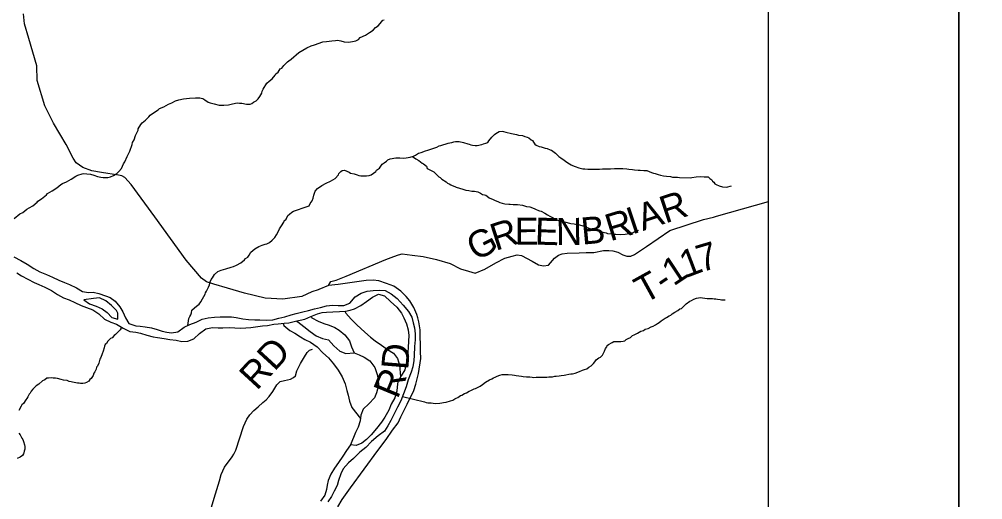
# Model space of a CAD drawing. Extents: x 0 to 39.3, y -3.9 to 22.
# Drawn here: x 7.125 to 9.15, y 19.017 to 20.026 of the extents above; entities that cross this region are included whole.
import ezdxf

# ---------------------------------------------------------------- set-up
doc = ezdxf.new("R2010")
doc.units = 0
for name, color, linetype in [('GM_X_Corporation', 7, 'Continuous'), ('GM_X_County_Road_Text', 7, 'Continuous'), ('GM_X_Major_River', 7, 'Continuous'), ('GM_X_Minor_River', 7, 'Continuous'), ('GM_X_Township_Road', 7, 'Continuous'), ('GM_X_Township_Road_Text', 7, 'Continuous'), ('SH_Data', 7, 'Continuous'), ('SH_Text', 7, 'Continuous')]:
    doc.layers.add(name, color=color, linetype=linetype)

msp = doc.modelspace()

# ---------------------------------------------------------------- linework, layer by layer
at = {"layer": 'GM_X_Corporation'}
msp.add_lwpolyline([(8.7, 17.1372), (8.7, 20.7), (3.278, 20.7)], dxfattribs=at)
at = {"layer": 'GM_X_Major_River'}
for points in [[(7.1136, 19.5274), (7.1283, 19.5199), (7.1414, 19.5121), (7.1554, 19.5031), (7.1681, 19.4957), (7.1821, 19.4905), (7.1949, 19.4846), (7.2081, 19.4787), (7.2202, 19.4735), (7.2304, 19.4692), (7.2451, 19.4625), (7.2579, 19.4547), (7.2708, 19.4529), (7.2803, 19.4531), (7.292, 19.4507), (7.3064, 19.4455), (7.3162, 19.4423), (7.3267, 19.4345), (7.3364, 19.4226), (7.3427, 19.4118), (7.3482, 19.3992), (7.3552, 19.3873), (7.3699, 19.3829), (7.3794, 19.3816), (7.3897, 19.3806), (7.4033, 19.3785), (7.4146, 19.3749), (7.4252, 19.3717), (7.4355, 19.3696), (7.4453, 19.3679), (7.4583, 19.37), (7.4717, 19.3797), (7.4836, 19.3852), (7.497, 19.3906), (7.5092, 19.3965), (7.5222, 19.3997), (7.5351, 19.401), (7.5473, 19.4016), (7.5572, 19.4018), (7.5708, 19.4012), (7.5807, 19.3999), (7.5947, 19.3974), (7.6068, 19.3961), (7.6201, 19.3951), (7.6304, 19.3949), (7.644, 19.3943), (7.6577, 19.3952), (7.6707, 19.3988), (7.6833, 19.4016), (7.6966, 19.4056), (7.7073, 19.4088), (7.7214, 19.412), (7.7333, 19.4149), (7.7459, 19.4185), (7.7584, 19.4213), (7.7706, 19.4245), (7.7832, 19.4262), (7.7957, 19.4256), (7.8075, 19.425), (7.8197, 19.4305), (7.8313, 19.4433), (7.844, 19.451), (7.8566, 19.4554), (7.8688, 19.4567), (7.8821, 19.4576), (7.8939, 19.4571), (7.9067, 19.4496), (7.9194, 19.4403), (7.9321, 19.426)], [(7.1202, 19.4938), (7.13, 19.4876), (7.1432, 19.4805), (7.156, 19.4738), (7.1658, 19.4691), (7.1786, 19.4636), (7.193, 19.4565), (7.2057, 19.4483), (7.2178, 19.4416), (7.2299, 19.4369), (7.2419, 19.4314), (7.2548, 19.4251), (7.2665, 19.4211), (7.2793, 19.4163), (7.2921, 19.4081), (7.3044, 19.3965), (7.3176, 19.3902), (7.3297, 19.3862), (7.3433, 19.378), (7.3572, 19.3709), (7.3701, 19.3696), (7.3799, 19.3671), (7.3932, 19.3631), (7.4064, 19.3595), (7.4159, 19.3578), (7.4295, 19.3557), (7.4417, 19.3539), (7.4545, 19.3522), (7.467, 19.3497), (7.4796, 19.3503), (7.4922, 19.3554), (7.5042, 19.3666), (7.5172, 19.3766), (7.531, 19.3791), (7.5431, 19.3785), (7.5526, 19.3787), (7.5659, 19.3789), (7.5781, 19.3787), (7.5906, 19.3777), (7.6012, 19.3783), (7.6119, 19.3792), (7.6263, 19.3809), (7.6362, 19.3826), (7.6465, 19.3836), (7.6599, 19.3864), (7.6694, 19.3867), (7.6819, 19.388), (7.6914, 19.389), (7.7055, 19.3925), (7.7154, 19.3943), (7.725, 19.3968), (7.738, 19.4022), (7.7518, 19.4081), (7.7617, 19.4106), (7.7712, 19.4116), (7.7841, 19.4121), (7.7982, 19.4127), (7.8107, 19.4136), (7.8203, 19.4153), (7.8298, 19.4186), (7.8428, 19.4252), (7.8551, 19.4338), (7.8674, 19.4431), (7.8801, 19.4493), (7.8929, 19.4457), (7.9056, 19.4337), (7.9184, 19.4221), (7.9284, 19.4094), (7.9336, 19.3994), (7.9387, 19.3868)], [(7.3324, 19.4093), (7.3294, 19.4147), (7.3186, 19.4251), (7.307, 19.4352), (7.2938, 19.4415), (7.2808, 19.4402), (7.2607, 19.4371)], [(7.2607, 19.4371), (7.2723, 19.4286), (7.2863, 19.4238), (7.2995, 19.4182), (7.31, 19.4105), (7.3197, 19.4), (7.3322, 19.3968), (7.3324, 19.4093)], [(7.9321, 19.426), (7.9433, 19.4129), (7.9499, 19.4006), (7.9528, 19.3892), (7.9557, 19.3785), (7.9574, 19.3656), (7.9572, 19.3534), (7.9558, 19.339), (7.9555, 19.32), (7.9546, 19.3101), (7.9521, 19.2968), (7.9485, 19.2851), (7.9425, 19.2689), (7.9381, 19.2545), (7.9329, 19.2401), (7.9274, 19.2254), (7.9203, 19.2118), (7.9062, 19.1839), (7.8999, 19.1726), (7.8925, 19.1617), (7.8798, 19.1513), (7.8656, 19.1394), (7.8532, 19.1274), (7.8409, 19.117), (7.8274, 19.1039), (7.817, 19.0946), (7.8061, 19.0822), (7.8007, 19.072), (7.7959, 19.0577), (7.7934, 19.0474), (7.7871, 19.0354), (7.7813, 19.0244), (7.7739, 19.0128)], [(7.9387, 19.3868), (7.9423, 19.3745), (7.9436, 19.3624), (7.9434, 19.3506), (7.9428, 19.3369), (7.9419, 19.327), (7.9406, 19.3176), (7.9385, 19.3031), (7.9352, 19.2899), (7.9278, 19.2779), (7.9208, 19.265), (7.9195, 19.2548), (7.9186, 19.2453), (7.9145, 19.2313), (7.9071, 19.2178), (7.9016, 19.2053), (7.8934, 19.191), (7.8867, 19.1805), (7.8763, 19.1669), (7.8647, 19.1535), (7.855, 19.1441), (7.8454, 19.1363), (7.8332, 19.1315), (7.821, 19.1329), (7.8132, 19.1209), (7.8051, 19.1088), (7.7961, 19.0957), (7.7879, 19.0836), (7.7801, 19.0708), (7.7746, 19.058), (7.7722, 19.0482), (7.7709, 19.0387), (7.7676, 19.0273), (7.7583, 19.0146)]]:
    msp.add_lwpolyline(points, dxfattribs=at)
at = {"layer": 'GM_X_Minor_River'}
for points in [[(7.6768, 19.924), (7.6814, 19.9292), (7.6888, 19.9371), (7.6915, 19.9393), (7.6965, 19.943), (7.7019, 19.9475), (7.7069, 19.9516), (7.7127, 19.9564), (7.7211, 19.9616), (7.7296, 19.9664), (7.7384, 19.9704), (7.7457, 19.9726), (7.7633, 19.9791), (7.7709, 19.9801), (7.7819, 19.9815), (7.7899, 19.9821), (7.7941, 19.9824), (7.8009, 19.9811), (7.8077, 19.9791), (7.8169, 19.9786), (7.8256, 19.9799), (7.8325, 19.9813), (7.8379, 19.9843), (7.8417, 19.988), (7.8525, 19.9932), (7.8613, 19.9987), (7.869, 20.0039), (7.874, 20.0091), (7.8794, 20.0128), (7.8837, 20.0173), (7.8891, 20.0245), (7.8922, 20.0255)], [(7.1145, 19.6079), (7.1265, 19.6176), (7.1322, 19.6206), (7.1411, 19.628), (7.1457, 19.6306), (7.1534, 19.635), (7.1626, 19.6421), (7.1642, 19.6447), (7.1715, 19.6492), (7.1823, 19.6577), (7.1846, 19.6607), (7.1938, 19.6659), (7.2038, 19.6725), (7.2123, 19.6796), (7.2161, 19.6818), (7.2242, 19.6851), (7.2341, 19.6906), (7.2441, 19.6973), (7.248, 19.6988), (7.2571, 19.7017), (7.2602, 19.7024), (7.267, 19.7022), (7.2746, 19.701), (7.2818, 19.6989), (7.2894, 19.6965), (7.2962, 19.6949), (7.3015, 19.694), (7.3072, 19.6939), (7.3114, 19.6942), (7.3171, 19.6957), (7.3232, 19.6986), (7.3298, 19.7027), (7.3344, 19.7068), (7.3398, 19.7131), (7.3438, 19.723), (7.3469, 19.7271), (7.3517, 19.738), (7.354, 19.7422), (7.3576, 19.7497), (7.3623, 19.7633), (7.3632, 19.7679), (7.3663, 19.7735), (7.3691, 19.7822), (7.3746, 19.7935), (7.3751, 19.7962), (7.3802, 19.8056), (7.3836, 19.8093), (7.3902, 19.8145), (7.3972, 19.8216), (7.4003, 19.8254), (7.4053, 19.8283), (7.4168, 19.8365), (7.4195, 19.8391), (7.4291, 19.8428), (7.4387, 19.8479), (7.4459, 19.8512), (7.4536, 19.8549), (7.4601, 19.857), (7.47, 19.8592), (7.4826, 19.8608), (7.4952, 19.8614), (7.5043, 19.8612), (7.5073, 19.8608), (7.5111, 19.86), (7.5152, 19.8572), (7.522, 19.8525), (7.5262, 19.8513), (7.5345, 19.8489), (7.5451, 19.8464), (7.555, 19.8459), (7.5645, 19.8469), (7.5729, 19.8486), (7.5832, 19.8507), (7.5877, 19.8506), (7.5931, 19.8502), (7.6025, 19.8485), (7.6078, 19.848), (7.6105, 19.8483), (7.6136, 19.8494), (7.6174, 19.8524), (7.6228, 19.8553), (7.6274, 19.8591), (7.6309, 19.864), (7.6349, 19.8715), (7.6357, 19.8753), (7.6376, 19.8794), (7.6451, 19.8926), (7.6501, 19.8963), (7.6563, 19.9015), (7.6632, 19.909), (7.6644, 19.9117), (7.6694, 19.9157), (7.6737, 19.9225), (7.6768, 19.924)], [(7.9964, 19.7557), (8.0025, 19.7582), (8.0078, 19.7604), (8.0113, 19.7615), (8.0178, 19.7637), (8.0205, 19.7644), (8.0266, 19.7666), (8.03, 19.7673), (8.0342, 19.7679), (8.0388, 19.7694), (8.0422, 19.7697), (8.0495, 19.77), (8.0589, 19.7679), (8.068, 19.7651), (8.0706, 19.7643), (8.0744, 19.7631), (8.0778, 19.7619), (8.0831, 19.7614), (8.0873, 19.7613), (8.0972, 19.7638), (8.1011, 19.7649), (8.106, 19.7663), (8.1099, 19.7678), (8.1122, 19.7715), (8.1184, 19.7786), (8.1242, 19.7842), (8.1269, 19.7865), (8.1338, 19.7909), (8.1399, 19.7916), (8.1429, 19.7908), (8.1479, 19.7891), (8.1596, 19.7867), (8.1706, 19.7842), (8.1744, 19.7834), (8.1831, 19.7825), (8.188, 19.7805), (8.1929, 19.7792), (8.1963, 19.7777), (8.2012, 19.7734), (8.2038, 19.7722), (8.2057, 19.7687), (8.209, 19.7645), (8.2117, 19.7618), (8.2181, 19.7594), (8.2222, 19.7586), (8.2306, 19.7558), (8.2347, 19.7549), (8.2412, 19.7525), (8.2438, 19.7514), (8.2494, 19.7475), (8.2524, 19.7451), (8.2595, 19.7381), (8.2633, 19.7358), (8.2704, 19.7307), (8.2734, 19.7288), (8.2783, 19.7253), (8.2855, 19.7206), (8.2881, 19.7194), (8.2934, 19.7174), (8.301, 19.7146), (8.3097, 19.7126), (8.3139, 19.7125), (8.3199, 19.712), (8.3348, 19.7117), (8.3412, 19.712), (8.345, 19.7119), (8.3511, 19.7122), (8.3599, 19.7124), (8.3678, 19.7127), (8.3766, 19.7129), (8.3891, 19.7131), (8.3941, 19.7134), (8.4024, 19.7121), (8.4062, 19.712), (8.4138, 19.7111), (8.418, 19.7103), (8.4263, 19.7098), (8.4305, 19.7093), (8.4377, 19.7088), (8.4446, 19.7087), (8.4491, 19.7067), (8.4544, 19.7047), (8.4582, 19.7031), (8.462, 19.7023), (8.4684, 19.7003), (8.4729, 19.6991), (8.4794, 19.6978), (8.4858, 19.6969), (8.4942, 19.696), (8.4983, 19.6952), (8.5021, 19.6951), (8.5086, 19.6946), (8.5128, 19.6942), (8.5352, 19.6938), (8.539, 19.6945), (8.5481, 19.6955), (8.5577, 19.6961), (8.5645, 19.6959), (8.5694, 19.6955), (8.5732, 19.6954), (8.577, 19.6919)], [(7.4794, 19.3832), (7.4813, 19.3981), (7.4836, 19.4022), (7.4856, 19.4056), (7.4872, 19.4098), (7.488, 19.4155), (7.4931, 19.4203), (7.4977, 19.424), (7.5035, 19.4281), (7.5066, 19.433), (7.5101, 19.439), (7.5156, 19.4492), (7.5164, 19.4522), (7.5184, 19.4556), (7.5227, 19.4639), (7.5251, 19.4688), (7.5263, 19.4753), (7.5283, 19.4798), (7.531, 19.4835), (7.5357, 19.4903), (7.5426, 19.4966), (7.5495, 19.4992), (7.5595, 19.5021), (7.5705, 19.5061), (7.5751, 19.5075), (7.582, 19.51), (7.5908, 19.5152), (7.5982, 19.5215), (7.6009, 19.5238), (7.6055, 19.5267), (7.6086, 19.5309), (7.6121, 19.5376), (7.6202, 19.544), (7.6287, 19.5495), (7.6356, 19.5521), (7.6421, 19.5539), (7.6455, 19.5546), (7.6509, 19.5575), (7.6563, 19.5624), (7.6621, 19.5683), (7.6656, 19.5736), (7.6687, 19.5789), (7.6719, 19.586), (7.6734, 19.5887), (7.6762, 19.5924), (7.6812, 19.6003), (7.682, 19.603), (7.6859, 19.6067), (7.6895, 19.6146), (7.6929, 19.6172), (7.6979, 19.6213), (7.7014, 19.6232), (7.7102, 19.6261), (7.7217, 19.6304), (7.7343, 19.6344), (7.7366, 19.6397), (7.7405, 19.6453), (7.7425, 19.6506), (7.7442, 19.6574), (7.7454, 19.6612), (7.747, 19.6653), (7.7516, 19.671), (7.7612, 19.6776), (7.7701, 19.6821), (7.7793, 19.6868), (7.7889, 19.6924), (7.7958, 19.6999), (7.7966, 19.7025), (7.8009, 19.7066), (7.804, 19.7092), (7.8089, 19.7099), (7.8187, 19.7052), (7.8214, 19.7032), (7.8289, 19.7016), (7.835, 19.6996), (7.8388, 19.6987), (7.8433, 19.6975), (7.8517, 19.6974), (7.8551, 19.6977), (7.8608, 19.6983), (7.865, 19.6998), (7.8746, 19.7065), (7.8758, 19.7095), (7.8824, 19.7139), (7.8878, 19.7222), (7.8921, 19.7248), (7.8971, 19.7285), (7.9001, 19.7311), (7.9047, 19.7337), (7.9166, 19.7358), (7.9253, 19.7352), (7.9329, 19.7347), (7.9382, 19.7354), (7.9466, 19.7368), (7.9539, 19.7393), (7.9577, 19.7411), (7.9643, 19.7456), (7.97, 19.7466), (7.9788, 19.7503), (7.9837, 19.7513), (7.9964, 19.7557)], [(7.9517, 19.7385), (7.9587, 19.7331), (7.9648, 19.7296), (7.9723, 19.7242), (7.9749, 19.723), (7.9809, 19.7179), (7.9823, 19.7133), (7.9884, 19.7106), (7.9963, 19.7059), (8.0008, 19.7016), (8.0071, 19.6958), (8.0098, 19.6942), (8.0135, 19.6907), (8.0226, 19.6852), (8.0255, 19.6825), (8.0289, 19.681), (8.0323, 19.679), (8.035, 19.6774), (8.0406, 19.675), (8.0437, 19.6739), (8.0505, 19.6715), (8.0576, 19.6694), (8.0637, 19.6674), (8.0698, 19.6666), (8.0762, 19.6657), (8.0789, 19.6656), (8.0819, 19.6652), (8.0887, 19.6639), (8.0944, 19.6616), (8.0989, 19.6588), (8.1027, 19.658), (8.1057, 19.6572), (8.1087, 19.6548), (8.1125, 19.6514), (8.1212, 19.6478), (8.1253, 19.6462), (8.131, 19.6438), (8.1351, 19.6418), (8.14, 19.6402), (8.1457, 19.639), (8.1541, 19.6381), (8.1567, 19.638), (8.1632, 19.6375), (8.1677, 19.6378), (8.1723, 19.6374), (8.1829, 19.6364), (8.1912, 19.6336), (8.1985, 19.6324), (8.2071, 19.6288), (8.2105, 19.628), (8.2162, 19.6252), (8.2188, 19.6244), (8.2223, 19.6236), (8.2298, 19.6196), (8.2354, 19.6157), (8.2403, 19.613), (8.2475, 19.6095), (8.252, 19.606), (8.2562, 19.6047), (8.263, 19.6023), (8.2671, 19.6011), (8.2739, 19.6002), (8.2819, 19.5982), (8.2846, 19.5978), (8.2914, 19.5965), (8.294, 19.5961), (8.2986, 19.5953), (8.3024, 19.5944), (8.3096, 19.5928), (8.316, 19.5908), (8.322, 19.588), (8.3292, 19.5856), (8.3318, 19.5844), (8.3372, 19.5832), (8.3436, 19.5815), (8.3489, 19.5803), (8.3587, 19.5778), (8.3618, 19.5767), (8.3697, 19.5758), (8.3735, 19.5753), (8.3788, 19.5748), (8.3899, 19.5746), (8.399, 19.5752), (8.4032, 19.5756), (8.4093, 19.5773), (8.4154, 19.5784), (8.4212, 19.5821), (8.4238, 19.5828), (8.4265, 19.5835)], [(8.577, 19.6919), (8.5807, 19.6892), (8.5822, 19.6865), (8.5848, 19.6842), (8.5874, 19.6807), (8.5901, 19.6795), (8.5965, 19.6764), (8.6033, 19.6747), (8.612, 19.6738), (8.622, 19.6767)], [(8.4144, 19.362), (8.4175, 19.3639), (8.4248, 19.3675), (8.4317, 19.3716), (8.437, 19.373), (8.4409, 19.3756), (8.447, 19.377), (8.4535, 19.3807), (8.4573, 19.3818), (8.4623, 19.3848), (8.4665, 19.3873), (8.4704, 19.3896), (8.4746, 19.3929), (8.4827, 19.3988), (8.4858, 19.4003), (8.4911, 19.4036), (8.4946, 19.4051), (8.4973, 19.4081), (8.5031, 19.4114), (8.5096, 19.4147), (8.5134, 19.4181), (8.5169, 19.4192), (8.5211, 19.4233), (8.5273, 19.4285), (8.5346, 19.4341), (8.5385, 19.4359), (8.5431, 19.4385), (8.5484, 19.4407), (8.5526, 19.4417), (8.5572, 19.442), (8.561, 19.4416), (8.5712, 19.4403), (8.575, 19.4402), (8.5826, 19.4401), (8.5857, 19.4396), (8.5891, 19.4396), (8.5929, 19.4388), (8.5982, 19.4379), (8.6012, 19.4375), (8.6088, 19.4373)], [(7.8096, 19.4135), (7.8118, 19.4095), (7.8229, 19.3963), (7.8345, 19.3844), (7.8514, 19.3693), (7.8634, 19.3588), (7.8735, 19.3514), (7.8863, 19.342), (7.8991, 19.3331), (7.9119, 19.3253), (7.9204, 19.3137), (7.9244, 19.3003), (7.9267, 19.2759)], [(7.6795, 19.3877), (7.6813, 19.3836), (7.694, 19.3731), (7.7042, 19.3672), (7.7159, 19.3598), (7.7256, 19.3539), (7.7373, 19.348), (7.7509, 19.3387), (7.7628, 19.3259), (7.7748, 19.3155), (7.7856, 19.3027), (7.7953, 19.2896), (7.8038, 19.2754), (7.81, 19.2609), (7.8139, 19.2471), (7.8164, 19.2372), (7.8193, 19.2246), (7.8244, 19.2112), (7.8421, 19.1878)], [(7.7073, 19.3928), (7.7103, 19.3907), (7.7231, 19.381), (7.7366, 19.3709), (7.7494, 19.3615), (7.7622, 19.3563), (7.7751, 19.3531), (7.7863, 19.3403), (7.799, 19.3291), (7.8115, 19.3243), (7.8293, 19.3258)], [(7.7384, 19.4024), (7.7401, 19.3997), (7.7533, 19.3926), (7.7654, 19.3878), (7.7767, 19.3842), (7.7881, 19.3791), (7.7978, 19.3736), (7.8091, 19.3639), (7.8195, 19.3512), (7.8235, 19.3382), (7.829, 19.3259), (7.8395, 19.3216), (7.8497, 19.3165), (7.8621, 19.309), (7.8722, 19.2952), (7.8776, 19.2802), (7.8797, 19.2699), (7.8799, 19.2574), (7.8758, 19.2419), (7.8715, 19.2317), (7.8598, 19.2186), (7.8479, 19.2078), (7.8427, 19.1953), (7.8417, 19.1828), (7.8373, 19.17), (7.8318, 19.1583), (7.821, 19.1329)], [(7.3397, 19.3801), (7.3395, 19.3777), (7.3372, 19.374), (7.3349, 19.3721), (7.3322, 19.3695), (7.3302, 19.3669), (7.3275, 19.3643), (7.3244, 19.3624), (7.3202, 19.3575), (7.3171, 19.3557), (7.3144, 19.3538), (7.3113, 19.3505), (7.3086, 19.3456), (7.3059, 19.3433), (7.3043, 19.3396), (7.3035, 19.3365), (7.3011, 19.3294), (7.2991, 19.3241), (7.2983, 19.3214), (7.2959, 19.315), (7.2943, 19.3124), (7.2931, 19.3071), (7.2919, 19.304), (7.2891, 19.298), (7.2876, 19.2957), (7.2864, 19.2916), (7.2855, 19.2886), (7.284, 19.2863), (7.282, 19.2833), (7.2801, 19.2784), (7.2761, 19.272), (7.2735, 19.2701), (7.2711, 19.2667), (7.2665, 19.2638), (7.2627, 19.2623), (7.2589, 19.2616), (7.2539, 19.2617), (7.2509, 19.2622), (7.2471, 19.2622), (7.2437, 19.2627), (7.2406, 19.2635), (7.2372, 19.2643), (7.2342, 19.2647), (7.23, 19.2656), (7.2255, 19.2675), (7.2179, 19.2688), (7.213, 19.27), (7.2054, 19.2717), (7.2009, 19.2725), (7.1959, 19.2726), (7.1921, 19.2731), (7.1864, 19.2728), (7.183, 19.2725), (7.1788, 19.2695), (7.1738, 19.2669), (7.1661, 19.2598), (7.1607, 19.2569), (7.1537, 19.2494), (7.1499, 19.2453), (7.1479, 19.2415), (7.1456, 19.2393), (7.1428, 19.2336), (7.1409, 19.2298), (7.1385, 19.2272), (7.1338, 19.2193), (7.1304, 19.2167), (7.1292, 19.2141), (7.1241, 19.2047)], [(7.9306, 19.234), (7.9768, 19.2229), (7.9805, 19.2216), (7.984, 19.2212), (7.9908, 19.2207), (7.995, 19.2203), (8.001, 19.2198), (8.009, 19.2204), (8.0132, 19.2207), (8.017, 19.2214), (8.0224, 19.2224), (8.0312, 19.2253), (8.0361, 19.2264), (8.0404, 19.229), (8.0434, 19.2308), (8.0469, 19.2323), (8.0526, 19.236), (8.0557, 19.2371), (8.0611, 19.2408), (8.0653, 19.2418), (8.0707, 19.2456), (8.0741, 19.2466), (8.081, 19.2503), (8.0841, 19.251), (8.0894, 19.2536), (8.094, 19.2562), (8.0987, 19.2595), (8.1052, 19.264), (8.1136, 19.2691), (8.1182, 19.2713), (8.1221, 19.2736), (8.1251, 19.275), (8.1294, 19.2772), (8.1351, 19.2787), (8.1404, 19.2801), (8.1442, 19.2804), (8.1477, 19.2807), (8.1526, 19.2806), (8.1613, 19.2797), (8.1659, 19.2793), (8.1697, 19.2784), (8.1811, 19.2767), (8.1841, 19.2763), (8.1913, 19.2758), (8.1955, 19.2753), (8.1985, 19.2753), (8.2031, 19.2748), (8.2069, 19.2744), (8.2118, 19.2747), (8.2213, 19.2745), (8.2259, 19.2748), (8.2343, 19.275), (8.2384, 19.2753), (8.2415, 19.2753), (8.2461, 19.2756), (8.2506, 19.2766), (8.2537, 19.2766), (8.2598, 19.2776), (8.2643, 19.2783), (8.2704, 19.2793), (8.2739, 19.2797), (8.2804, 19.2811), (8.2846, 19.2817), (8.288, 19.2821), (8.2933, 19.2831), (8.3025, 19.2864), (8.309, 19.2897), (8.3132, 19.2908), (8.3182, 19.2926), (8.3221, 19.2959), (8.327, 19.2989), (8.3321, 19.3037), (8.3348, 19.3067), (8.3379, 19.3112), (8.3437, 19.3153), (8.3467, 19.3168), (8.351, 19.3209), (8.3553, 19.3292), (8.3577, 19.3349), (8.36, 19.3382), (8.3608, 19.3416), (8.3639, 19.3431), (8.3712, 19.3476), (8.375, 19.3494), (8.3788, 19.3497), (8.383, 19.35), (8.3899, 19.3499), (8.3948, 19.3502), (8.3983, 19.3509), (8.4006, 19.3539), (8.4048, 19.3557), (8.4102, 19.3583), (8.4144, 19.362)], [(7.124, 19.1575), (7.127, 19.1536), (7.1307, 19.1467), (7.1326, 19.1437), (7.1336, 19.1395), (7.1358, 19.1326), (7.1365, 19.1291), (7.1364, 19.1234), (7.1352, 19.1193), (7.1348, 19.1162), (7.134, 19.114), (7.1316, 19.1102), (7.1266, 19.1069), (7.1209, 19.1043)]]:
    msp.add_lwpolyline(points, dxfattribs=at)
at = {"layer": 'GM_X_Township_Road'}
msp.add_line((8.591, 19.6129), (8.7, 19.6436), dxfattribs=at)
for points in [[(7.7533, 19.4585), (7.7401, 19.4538), (7.7191, 19.4442), (7.6788, 19.4388), (7.6421, 19.441), (7.5986, 19.4513), (7.5628, 19.4616), (7.5338, 19.4701), (7.5189, 19.475), (7.5078, 19.4828), (7.4759, 19.5203), (7.4098, 19.6116), (7.3605, 19.6793), (7.347, 19.6943), (7.3404, 19.6974), (7.3333, 19.6993), (7.2982, 19.7048), (7.2777, 19.708), (7.2584, 19.7149), (7.2449, 19.7253), (7.2381, 19.7348), (7.2239, 19.7636), (7.1972, 19.8081), (7.1788, 19.845), (7.1625, 19.8981), (7.1617, 19.9289), (7.145, 19.9863), (7.1361, 20.0172), (7.1337, 20.0376)], [(7.7754, 19.4671), (7.78, 19.4754), (7.7915, 19.4788), (7.8125, 19.4868), (7.8959, 19.5219), (7.9122, 19.5281), (7.9221, 19.532), (7.9297, 19.5341), (7.9507, 19.5313), (7.9743, 19.5279), (8.0019, 19.5217), (8.0305, 19.5134), (8.0528, 19.5026), (8.0692, 19.4974), (8.0834, 19.493), (8.1039, 19.5019), (8.1271, 19.5151), (8.1455, 19.5245), (8.1611, 19.5291), (8.1716, 19.532), (8.181, 19.5301), (8.2029, 19.5187), (8.2166, 19.511), (8.227, 19.5089), (8.2375, 19.5099), (8.2499, 19.525), (8.2588, 19.5309), (8.2665, 19.534), (8.2765, 19.5352), (8.3019, 19.5357), (8.3164, 19.5363), (8.3327, 19.5369), (8.3532, 19.5406), (8.3641, 19.5409), (8.3729, 19.54), (8.3834, 19.5372), (8.394, 19.5318), (8.402, 19.5289), (8.4105, 19.5286), (8.418, 19.5324), (8.4439, 19.5494), (8.4924, 19.5825), (8.5631, 19.6059), (8.5845, 19.611), (8.591, 19.6129)], [(7.795, 19.0024), (7.804, 19.018), (7.8215, 19.0426), (7.8785, 19.1208), (7.8962, 19.1439), (7.9096, 19.1636), (7.9214, 19.179), (7.9273, 19.1913), (7.9406, 19.218), (7.9543, 19.2468), (7.9588, 19.2601), (7.9641, 19.2822), (7.9689, 19.3142), (7.9687, 19.3285), (7.9678, 19.3743), (7.9653, 19.3908), (7.9632, 19.3992), (7.9606, 19.4067), (7.9543, 19.4209), (7.9457, 19.4348), (7.9384, 19.4442), (7.9271, 19.4557), (7.9122, 19.4658), (7.8973, 19.4718), (7.8812, 19.4769), (7.8692, 19.4788), (7.854, 19.4776), (7.7953, 19.4697), (7.7754, 19.4671), (7.755, 19.4591), (7.7533, 19.4585)], [(7.529, 19.0016), (7.5345, 19.0208), (7.546, 19.0573), (7.5492, 19.0704), (7.5566, 19.0858), (7.5728, 19.1075), (7.5763, 19.1131), (7.5803, 19.1217), (7.5964, 19.1714), (7.6033, 19.1864), (7.6096, 19.1954), (7.6182, 19.2046), (7.6271, 19.2124), (7.6371, 19.2218), (7.6437, 19.2274), (7.6506, 19.2343), (7.6578, 19.2446), (7.6667, 19.2588), (7.6732, 19.2656), (7.6828, 19.268), (7.6953, 19.2704), (7.7018, 19.2738), (7.7057, 19.2778), (7.7086, 19.2879), (7.716, 19.3038), (7.7245, 19.3178), (7.7299, 19.3269), (7.7353, 19.3315), (7.7412, 19.3338)]]:
    msp.add_lwpolyline(points, dxfattribs=at)
at = {"layer": 'SH_Data'}
msp.add_lwpolyline([(1.9, 21.1), (9.1, 21.1), (9.1, 13.9), (1.9, 13.9)], close=True, dxfattribs=at)
at = {"layer": 'SH_Text'}
msp.add_lwpolyline([(9.1, 21.1), (11.7047, 21.1), (11.7047, 13.9), (9.1, 13.9)], close=True, dxfattribs=at)

# ---------------------------------------------------------------- texts
at = {"layer": 'GM_X_County_Road_Text'}
for s, rotation, p in [('D', 85.3807, (7.9425, 19.2889)), ('R', 67.5158, (7.9202, 19.2273))]:
    msp.add_text(s, height=0.0568, rotation=rotation, dxfattribs=at).set_placement(p)
at = {"layer": 'GM_X_Township_Road_Text'}
for s, height, rotation, p in [('R', 0.0568, 18.3634, (8.483, 19.5973)), ('I', 0.0568, 18.4655, (8.4134, 19.574)), ('A', 0.0568, 18.5657, (8.4357, 19.5814)), ('E', 0.0568, 0.15, (8.1663, 19.5532)), ('E', 0.0568, 358.2341, (8.2083, 19.5534)), ('N', 0.0568, 0.8092, (8.2536, 19.552)), ('B', 0.0568, 5.3907, (8.3085, 19.553)), ('R', 0.0568, 16.994, (8.3673, 19.5598)), ('G', 0.0568, 27.1858, (8.0842, 19.5178)), ('R', 0.0568, 17.8055, (8.1264, 19.5397)), ('7', 0.0568, 16.6145, (8.5581, 19.4947)), ('1', 0.0568, 33.4404, (8.5002, 19.4649)), ('1', 0.0568, 20.7558, (8.5264, 19.4827)), ('T', 0.0568, 28.9289, (8.4389, 19.4281)), ('-', 0.0568, 34.4641, (8.4812, 19.4518)), ('RD', 0.05682, 47.433, (7.6244, 19.2451))]:
    msp.add_text(s, height=height, rotation=rotation, dxfattribs=at).set_placement(p)

doc.saveas('drawing.dxf')
